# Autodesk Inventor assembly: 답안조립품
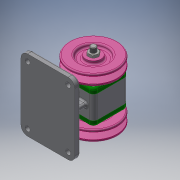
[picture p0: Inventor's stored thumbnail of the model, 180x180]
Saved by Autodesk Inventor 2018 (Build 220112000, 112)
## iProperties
Created: 2020-11
Part Number: 답안조립품
Document SubType Name: Assembly
Designer: Administrator
Author: Administrator
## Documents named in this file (10)
- C:\Users\Administrator\Desktop\701106V1053\답안조립품.iam
- C:\Users\Administrator\Desktop\701106V1053\본체.ipt
- C:\Users\Administrator\Desktop\701106V1053\V-벨트풀리.ipt
- C:\Users\Administrator\Desktop\701106V1053\베어링 6004.ipt
- C:\Users\Administrator\Desktop\701106V1053\오일 실 17 30 5.ipt
- C:\Users\Administrator\Desktop\701106V1053\축.ipt
- C:\Users\Administrator\Desktop\701106V1053\커버.ipt
- C:\Users\Administrator\Desktop\701106V1053\키 5 x 5 x 12.ipt
- C:\Users\Administrator\Desktop\701106V1053\너트 M10x1.ipt
- C:\Users\Administrator\Desktop\701106V1053\볼트 M4.ipt
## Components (2 placed, 1 different names)
1. V-벨트풀리:1
2. V-벨트풀리:2
